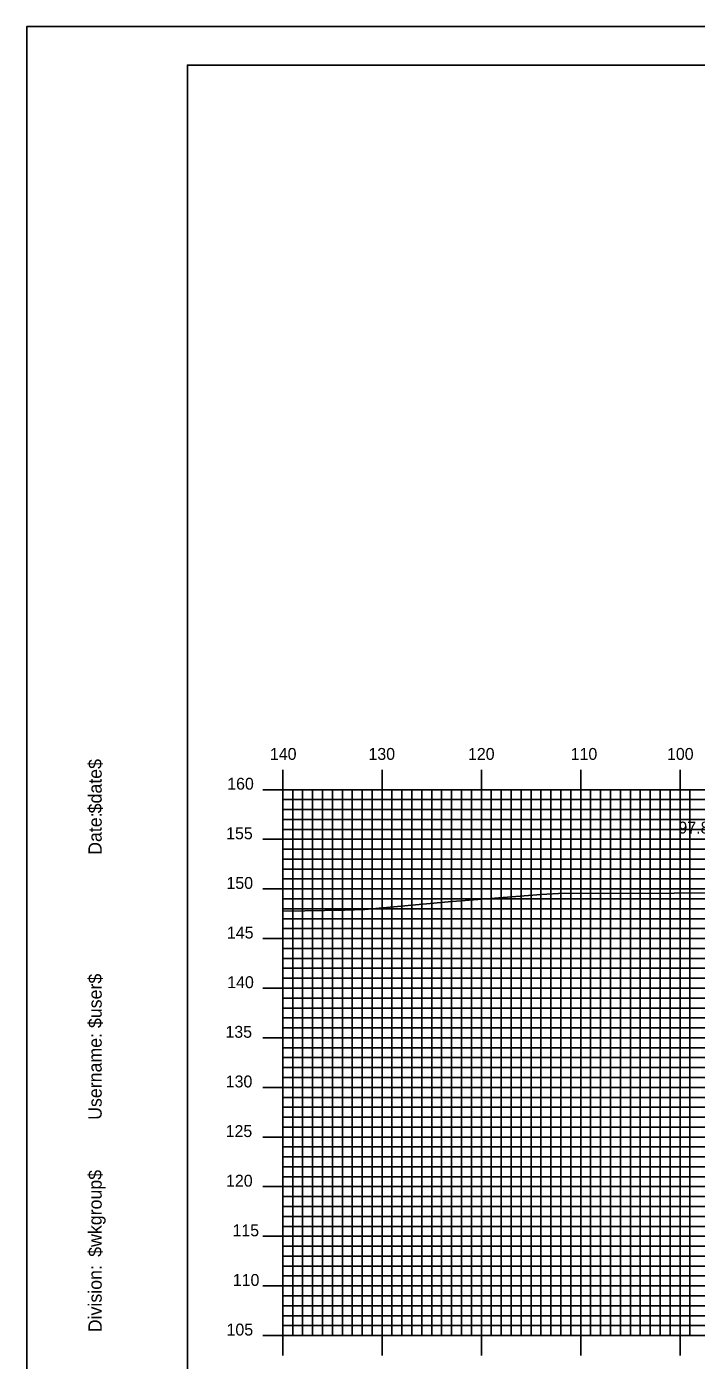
# Model space of a CAD drawing. Extents: x 1769661 to 1770005, y 442591 to 442811.
# Drawn here: x 1769661.2 to 1769728.6, y 442676.2 to 442810.5 of the extents above; entities that cross this region are included whole.
import ezdxf

# ---------------------------------------------------------------- set-up
doc = ezdxf.new("R2010")
doc.units = 0
for name, color, linetype in [('BORDER', 7, 'Continuous'), ('D_Text_Standard', 7, 'Continuous'), ('H_V ANNOTATION', 7, 'Continuous'), ('MAJOR', 7, 'Continuous'), ('MINOR', 7, 'Continuous'), ('PLOT BOUNDARY', 7, 'Continuous'), ('S_Roadway_Centerline', 7, 'Continuous')]:
    doc.layers.add(name, color=color, linetype=linetype)

msp = doc.modelspace()

# ---------------------------------------------------------------- linework, layer by layer
at = {"layer": 'BORDER'}
msp.add_lwpolyline([(1769677.41, 442596.67), (1769997.41, 442596.67), (1769997.41, 442806.67), (1769677.41, 442806.67)], close=True, dxfattribs=at)
at = {"layer": 'MAJOR'}
for p, q in [((1769687.01, 442735.67), (1769687.01, 442733.67)), ((1769697.01, 442735.67), (1769697.01, 442733.67)), ((1769707.01, 442735.67), (1769707.01, 442733.67)), ((1769717.01, 442735.67), (1769717.01, 442733.67)), ((1769727.01, 442735.67), (1769727.01, 442733.67)), ((1769685.01, 442733.67), (1769687.01, 442733.67)), ((1769687.01, 442733.67), (1769967.01, 442733.67)), ((1769687.01, 442678.67), (1769687.01, 442733.67)), ((1769687.01, 442678.67), (1769687.01, 442733.67)), ((1769687.01, 442733.67), (1769967.01, 442733.67)), ((1769697.01, 442678.67), (1769697.01, 442733.67)), ((1769707.01, 442678.67), (1769707.01, 442733.67)), ((1769717.01, 442678.67), (1769717.01, 442733.67)), ((1769727.01, 442678.67), (1769727.01, 442733.67)), ((1769685.01, 442728.67), (1769687.01, 442728.67)), ((1769687.01, 442728.67), (1769967.01, 442728.67)), ((1769685.01, 442723.67), (1769687.01, 442723.67)), ((1769687.01, 442723.67), (1769967.01, 442723.67)), ((1769685.01, 442718.67), (1769687.01, 442718.67)), ((1769687.01, 442718.67), (1769967.01, 442718.67)), ((1769685.01, 442713.67), (1769687.01, 442713.67)), ((1769687.01, 442713.67), (1769967.01, 442713.67)), ((1769685.01, 442708.67), (1769687.01, 442708.67)), ((1769687.01, 442708.67), (1769967.01, 442708.67)), ((1769685.01, 442703.67), (1769687.01, 442703.67)), ((1769687.01, 442703.67), (1769967.01, 442703.67)), ((1769685.01, 442698.67), (1769687.01, 442698.67)), ((1769687.01, 442698.67), (1769967.01, 442698.67)), ((1769685.01, 442693.67), (1769687.01, 442693.67)), ((1769687.01, 442693.67), (1769967.01, 442693.67)), ((1769685.01, 442688.67), (1769687.01, 442688.67)), ((1769687.01, 442688.67), (1769967.01, 442688.67)), ((1769685.01, 442683.67), (1769687.01, 442683.67)), ((1769687.01, 442683.67), (1769967.01, 442683.67)), ((1769685.01, 442678.67), (1769687.01, 442678.67)), ((1769687.01, 442678.67), (1769967.01, 442678.67)), ((1769687.01, 442678.67), (1769967.01, 442678.67)), ((1769687.01, 442676.66), (1769687.01, 442678.67)), ((1769697.01, 442676.66), (1769697.01, 442678.67)), ((1769707.01, 442676.66), (1769707.01, 442678.67)), ((1769717.01, 442676.66), (1769717.01, 442678.67)), ((1769727.01, 442676.66), (1769727.01, 442678.67))]:
    msp.add_line(p, q, dxfattribs=at)
at = {"layer": 'MINOR'}
for p, q in [((1769687.01, 442732.67), (1769967.01, 442732.67)), ((1769687.01, 442732.67), (1769689.02, 442732.67)), ((1769688.01, 442678.67), (1769688.01, 442733.67)), ((1769689.01, 442678.67), (1769689.01, 442733.67)), ((1769690.01, 442678.67), (1769690.01, 442733.67)), ((1769691.01, 442678.67), (1769691.01, 442733.67)), ((1769692.01, 442678.67), (1769692.01, 442733.67)), ((1769693.01, 442678.67), (1769693.01, 442733.67)), ((1769694.01, 442678.67), (1769694.01, 442733.67)), ((1769695.01, 442678.67), (1769695.01, 442733.67)), ((1769696.01, 442678.67), (1769696.01, 442733.67)), ((1769698.01, 442678.67), (1769698.01, 442733.67)), ((1769699.01, 442678.67), (1769699.01, 442733.67)), ((1769700.01, 442678.67), (1769700.01, 442733.67)), ((1769701.01, 442678.67), (1769701.01, 442733.67)), ((1769702.01, 442678.67), (1769702.01, 442733.67)), ((1769703.01, 442678.67), (1769703.01, 442733.67)), ((1769704.01, 442678.67), (1769704.01, 442733.67)), ((1769705.01, 442678.67), (1769705.01, 442733.67)), ((1769706.01, 442678.67), (1769706.01, 442733.67)), ((1769708.01, 442678.67), (1769708.01, 442733.67)), ((1769709.01, 442678.67), (1769709.01, 442733.67)), ((1769710.01, 442678.67), (1769710.01, 442733.67)), ((1769711.01, 442678.67), (1769711.01, 442733.67)), ((1769712.01, 442678.67), (1769712.01, 442733.67)), ((1769713.01, 442678.67), (1769713.01, 442733.67)), ((1769714.01, 442678.67), (1769714.01, 442733.67)), ((1769715.01, 442678.67), (1769715.01, 442733.67)), ((1769716.01, 442678.67), (1769716.01, 442733.67)), ((1769718.01, 442678.67), (1769718.01, 442733.67)), ((1769719.01, 442678.67), (1769719.01, 442733.67)), ((1769720.01, 442678.67), (1769720.01, 442733.67)), ((1769721.01, 442678.67), (1769721.01, 442733.67)), ((1769722.01, 442678.67), (1769722.01, 442733.67)), ((1769723.01, 442678.67), (1769723.01, 442733.67)), ((1769724.01, 442678.67), (1769724.01, 442733.67)), ((1769725.01, 442678.67), (1769725.01, 442733.67)), ((1769726.01, 442678.67), (1769726.01, 442733.67)), ((1769728.01, 442678.67), (1769728.01, 442733.67)), ((1769687.01, 442731.67), (1769967.01, 442731.67)), ((1769687.01, 442731.67), (1769689.02, 442731.67)), ((1769687.01, 442730.67), (1769967.01, 442730.67)), ((1769687.01, 442730.67), (1769689.02, 442730.67)), ((1769687.01, 442729.67), (1769967.01, 442729.67)), ((1769687.01, 442729.67), (1769689.02, 442729.67)), ((1769687.01, 442727.67), (1769967.01, 442727.67)), ((1769687.01, 442727.67), (1769689.02, 442727.67)), ((1769687.01, 442726.67), (1769967.01, 442726.67)), ((1769687.01, 442726.67), (1769689.02, 442726.67)), ((1769687.01, 442725.67), (1769967.01, 442725.67)), ((1769687.01, 442725.67), (1769689.02, 442725.67)), ((1769687.01, 442724.67), (1769967.01, 442724.67)), ((1769687.01, 442724.67), (1769689.02, 442724.67)), ((1769687.01, 442722.67), (1769967.01, 442722.67)), ((1769687.01, 442722.67), (1769689.02, 442722.67)), ((1769687.01, 442721.67), (1769967.01, 442721.67)), ((1769687.01, 442721.67), (1769689.02, 442721.67)), ((1769687.01, 442720.67), (1769967.01, 442720.67)), ((1769687.01, 442720.67), (1769689.02, 442720.67)), ((1769687.01, 442719.67), (1769967.01, 442719.67)), ((1769687.01, 442719.67), (1769689.02, 442719.67)), ((1769687.01, 442717.67), (1769967.01, 442717.67)), ((1769687.01, 442717.67), (1769689.02, 442717.67)), ((1769687.01, 442716.67), (1769967.01, 442716.67)), ((1769687.01, 442716.67), (1769689.02, 442716.67)), ((1769687.01, 442715.67), (1769967.01, 442715.67)), ((1769687.01, 442715.67), (1769689.02, 442715.67)), ((1769687.01, 442714.67), (1769967.01, 442714.67)), ((1769687.01, 442714.67), (1769689.02, 442714.67)), ((1769687.01, 442712.67), (1769967.01, 442712.67)), ((1769687.01, 442712.67), (1769689.02, 442712.67)), ((1769687.01, 442711.67), (1769967.01, 442711.67)), ((1769687.01, 442711.67), (1769689.02, 442711.67)), ((1769687.01, 442710.67), (1769967.01, 442710.67)), ((1769687.01, 442710.67), (1769689.02, 442710.67)), ((1769687.01, 442709.67), (1769967.01, 442709.67)), ((1769687.01, 442709.67), (1769689.02, 442709.67)), ((1769687.01, 442707.67), (1769967.01, 442707.67)), ((1769687.01, 442707.67), (1769689.02, 442707.67)), ((1769687.01, 442706.67), (1769967.01, 442706.67)), ((1769687.01, 442706.67), (1769689.02, 442706.67)), ((1769687.01, 442705.67), (1769967.01, 442705.67)), ((1769687.01, 442705.67), (1769689.02, 442705.67)), ((1769687.01, 442704.67), (1769967.01, 442704.67)), ((1769687.01, 442704.67), (1769689.02, 442704.67)), ((1769687.01, 442702.67), (1769967.01, 442702.67)), ((1769687.01, 442702.67), (1769689.02, 442702.67)), ((1769687.01, 442701.67), (1769967.01, 442701.67)), ((1769687.01, 442701.67), (1769689.02, 442701.67)), ((1769687.01, 442700.67), (1769967.01, 442700.67)), ((1769687.01, 442700.67), (1769689.02, 442700.67)), ((1769687.01, 442699.67), (1769967.01, 442699.67)), ((1769687.01, 442699.67), (1769689.02, 442699.67)), ((1769687.01, 442697.67), (1769967.01, 442697.67)), ((1769687.01, 442697.67), (1769689.02, 442697.67)), ((1769687.01, 442696.67), (1769967.01, 442696.67)), ((1769687.01, 442696.67), (1769689.02, 442696.67)), ((1769687.01, 442695.67), (1769967.01, 442695.67)), ((1769687.01, 442695.67), (1769689.02, 442695.67)), ((1769687.01, 442694.67), (1769967.01, 442694.67)), ((1769687.01, 442694.67), (1769689.02, 442694.67)), ((1769687.01, 442692.67), (1769967.01, 442692.67)), ((1769687.01, 442692.67), (1769689.02, 442692.67)), ((1769687.01, 442691.67), (1769967.01, 442691.67)), ((1769687.01, 442691.67), (1769689.02, 442691.67)), ((1769687.01, 442690.67), (1769967.01, 442690.67)), ((1769687.01, 442690.67), (1769689.02, 442690.67)), ((1769687.01, 442689.67), (1769967.01, 442689.67)), ((1769687.01, 442689.67), (1769689.02, 442689.67)), ((1769687.01, 442687.67), (1769967.01, 442687.67)), ((1769687.01, 442687.67), (1769689.02, 442687.67)), ((1769687.01, 442686.67), (1769967.01, 442686.67)), ((1769687.01, 442686.67), (1769689.02, 442686.67)), ((1769687.01, 442685.67), (1769967.01, 442685.67)), ((1769687.01, 442685.67), (1769689.02, 442685.67)), ((1769687.01, 442684.67), (1769967.01, 442684.67)), ((1769687.01, 442684.67), (1769689.02, 442684.67)), ((1769687.01, 442682.67), (1769967.01, 442682.67)), ((1769687.01, 442682.67), (1769689.02, 442682.67)), ((1769687.01, 442681.67), (1769967.01, 442681.67)), ((1769687.01, 442681.67), (1769689.02, 442681.67)), ((1769687.01, 442680.67), (1769967.01, 442680.67)), ((1769687.01, 442680.67), (1769689.02, 442680.67)), ((1769687.01, 442679.67), (1769967.01, 442679.67)), ((1769687.01, 442679.67), (1769689.02, 442679.67))]:
    msp.add_line(p, q, dxfattribs=at)
at = {"layer": 'PLOT BOUNDARY'}
msp.add_lwpolyline([(1769661.23, 442590.55), (1770001.23, 442590.55), (1770001.23, 442810.55), (1769661.23, 442810.55)], close=True, dxfattribs=at)
at = {"layer": 'S_Roadway_Centerline'}
msp.add_lwpolyline([(1769687.01, 442721.44), (1769689.25, 442721.46), (1769693.22, 442721.54), (1769695.28, 442721.6), (1769703.66, 442722.36), (1769713.02, 442723.12), (1769715.36, 442723.25), (1769719.42, 442723.21), (1769733.43, 442723.28)], dxfattribs=at)

# ---------------------------------------------------------------- texts
at = {"layer": 'BORDER'}
for s, p in [('$date$', (1769668.78, 442731.28)), ('Date:', (1769668.78, 442727.1)), ('$user$', (1769668.78, 442709.65)), ('Username:', (1769668.78, 442700.4)), ('$wkgroup$', (1769668.78, 442686.6)), ('Division:', (1769668.78, 442679))]:
    msp.add_text(s, height=1.339, rotation=90, dxfattribs=at).set_placement(p)
at = {"layer": 'D_Text_Standard'}
msp.add_text("97.8'", height=1.2, dxfattribs=at).set_placement((1769726.85, 442729.25))
at = {"layer": 'H_V ANNOTATION'}
for s, p in [('140', (1769685.72, 442736.67)), ('130', (1769695.64, 442736.67)), ('120', (1769705.66, 442736.67)), ('110', (1769716, 442736.67)), ('100', (1769725.7, 442736.67)), ('160', (1769681.42, 442733.67)), ('155', (1769681.31, 442728.67)), ('150', (1769681.34, 442723.67)), ('145', (1769681.39, 442718.67)), ('140', (1769681.42, 442713.67)), ('135', (1769681.24, 442708.67)), ('130', (1769681.27, 442703.67)), ('125', (1769681.26, 442698.67)), ('120', (1769681.3, 442693.67)), ('115', (1769681.95, 442688.67)), ('110', (1769681.98, 442683.67)), ('105', (1769681.35, 442678.67))]:
    msp.add_text(s, height=1.2, dxfattribs=at).set_placement(p)
at = {"layer": 'MAJOR'}
msp.add_text('-', height=0.012, dxfattribs=at).set_placement((1769687.01, 442678.67))

doc.saveas('drawing.dxf')
